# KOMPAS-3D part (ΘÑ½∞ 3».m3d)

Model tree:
1. Эскиз:1
2. Операция выдавливания:1
     Расстояние 1 = 2
3. Эскиз:2
4. Операция выдавливания:2
     Расстояние 1 = 5
5. Эскиз:3
6. Операция выдавливания:3
     Расстояние 1 = 2
7. Эскиз:4
8. Операция выдавливания:4
     Расстояние 1 = 78
9. Эскиз:5
10. Операция выдавливания:5
     Расстояние 1 = 2
11. Эскиз:6
12. Операция выдавливания:6
     Расстояние 1 = 4.5
13. Эскиз:7
14. Операция выдавливания:7
     Расстояние 1 = 2
15. Скругление:1
     Радиус = 1
16. Скругление:2
     Радиус = 1
17. Эскиз:8
18. Вырезать элемент выдавливания:1
     Расстояние 1 = 10; Угол 1 = 35
19. Эскиз:9
20. Вырезать элемент выдавливания:2
     Расстояние 1 = 10; Угол 1 = 35
21. Эскиз:10
22. Вырезать элемент выдавливания:3
     Расстояние 2 = 22; Расстояние 1 = 22; Угол 1 = 35
23. Эскиз:11
24. Вырезать элемент выдавливания:4
     Расстояние 2 = 2; Расстояние 1 = 2
25. Эскиз:12
26. Вырезать элемент выдавливания:5
     Расстояние 2 = 2; Расстояние 1 = 2; Угол 1 = 35
27. Эскиз:13
28. Вырезать элемент выдавливания:6
     Расстояние 2 = 2; Расстояние 1 = 122
29. Эскиз:14
30. Вырезать элемент выдавливания:7
     Расстояние 2 = 100; Расстояние 1 = 60
